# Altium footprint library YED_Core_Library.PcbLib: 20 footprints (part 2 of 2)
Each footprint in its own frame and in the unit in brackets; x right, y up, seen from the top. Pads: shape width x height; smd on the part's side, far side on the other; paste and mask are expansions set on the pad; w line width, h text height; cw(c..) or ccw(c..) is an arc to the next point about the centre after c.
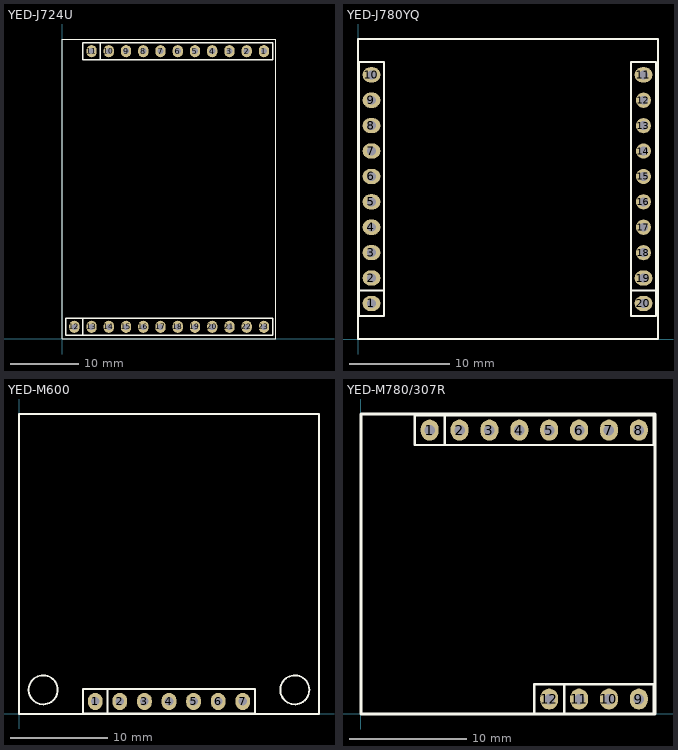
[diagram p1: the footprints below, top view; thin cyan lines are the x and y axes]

## YED-J724U [mil]
pads (23):
  oval 60x70 hole 35: 1(1170.87,1669.29) 2(1070.87,1669.29) 3(970.87,1669.29) 4(870.87,1669.29) 5(770.87,1669.29) 6(670.87,1669.29) 7(570.87,1669.29) 8(470.87,1669.29) 9(370.87,1669.29) 10(270.87,1669.29) 11(170.87,1669.29) 12(70.87,70.87) 13(170.87,70.87) 14(270.87,70.87) 15(370.87,70.87) 16(470.87,70.87) 17(570.87,70.87) 18(670.87,70.87) 19(770.87,70.87) 20(870.87,70.87) 21(970.87,70.87) 22(1070.87,70.87) 23(1170.87,70.87)
Top Overlay:
  lines w5: 0,0 1240.16,0 1240.16,1740.16 0,1740.16 0,0
  lines w7.87: 120.87,20.87 120.87,120.87 ; 220.87,1619.29 220.87,1719.29 ; 20.87,20.87 1220.87,20.87 1220.87,120.87 20.87,120.87 20.87,20.87 ; 120.87,1619.29 120.87,1719.29 1220.87,1719.29 1220.87,1619.29 120.87,1619.29

## YED-J780YQ [mil]
pads (20):
  oval 70x60 hole 35: 1(53.12,140.06) 2(53.12,240.06) 3(53.12,340.06) 4(53.12,440.06) 5(53.12,540.06) 6(53.12,640.06) 7(53.12,740.06) 8(53.12,840.06) 9(53.12,940.06) 10(53.12,1040.06) 11(1124,1040) 19(1124,240) 20(1124,140)
  oval 59.06x60 hole 35: 12(1124,940) 13(1124,840) 14(1124,740) 15(1124,640) 16(1124,540) 17(1124,440) 18(1124,340)
Top Overlay:
  lines w7.87: 3.12,190.06 103.12,190.06 ; 1074,190 1174,190 ; 3.12,90.13 103.12,90.13 103.12,1089.93 3.12,1089.93 3.12,90.13 ; 1074,90.06 1174,90.06 1174,1089.87 1074,1089.87 1074,90.06
  lines w8: 0,0 1181.1,0 1181.1,1181.1 0,1181.1 0,0

## YED-M600 [mil]
pads (7):
  oval 60x70 hole 35: 1(310.24,51.18) 2(410.24,51.18) 3(510.24,51.18) 4(610.24,51.18) 5(710.24,51.18) 6(810.24,51.18) 7(910.24,51.18)
Top Overlay:
  circle w7.87: c98.42,98.43 r59.06
  circle w7.87: c1122.05,98.42 r59.06
  lines w7.87: 360.24,1.18 360.24,101.18 ; 664.57,101.18 260.24,101.18 ; 260.24,101.18 960.24,101.18 960.24,1.18 260.24,1.18 260.24,101.18
  lines w10: 0,0 1220.47,0 1220.47,1220.47 0,1220.47 0,0

## YED-M780/307R [mil]
pads (12):
  oval 60x70 hole 35: 1(230,950) 2(330,950) 3(430,950) 4(530,950) 5(630,950) 6(730,950) 7(830,950) 8(930,950) 9(930,50) 10(830,50) 11(730,50) 12(630,50)
Top Overlay:
  lines w7.87: 280,900 280,1000 ; 584.33,900 180,900 ; 680,0 680,100 ; 180,900 980,900 980,1000 180,1000 180,900 ; 580,0 980,0 980,100 580,100 580,75 580,25 580,0
  lines w10: 0,0 984.25,0 984.25,1003.94 0,1003.94 0,0
3D body: height 43.31, standoff 0, extent 783.17,4.01 974.6,95.63
3D body: height 354.33, standoff -86.61, extent 807.64,28.39 851.16,72
3D body: height 354.33, standoff -86.61, extent 907.64,28.39 951.16,72
3D body: height 43.31, standoff 0, extent 583.17,4.01 774.6,95.63
3D body: height 354.33, standoff -86.61, extent 607.64,28.39 651.16,72
3D body: height 354.33, standoff -86.61, extent 707.64,28.39 751.16,72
